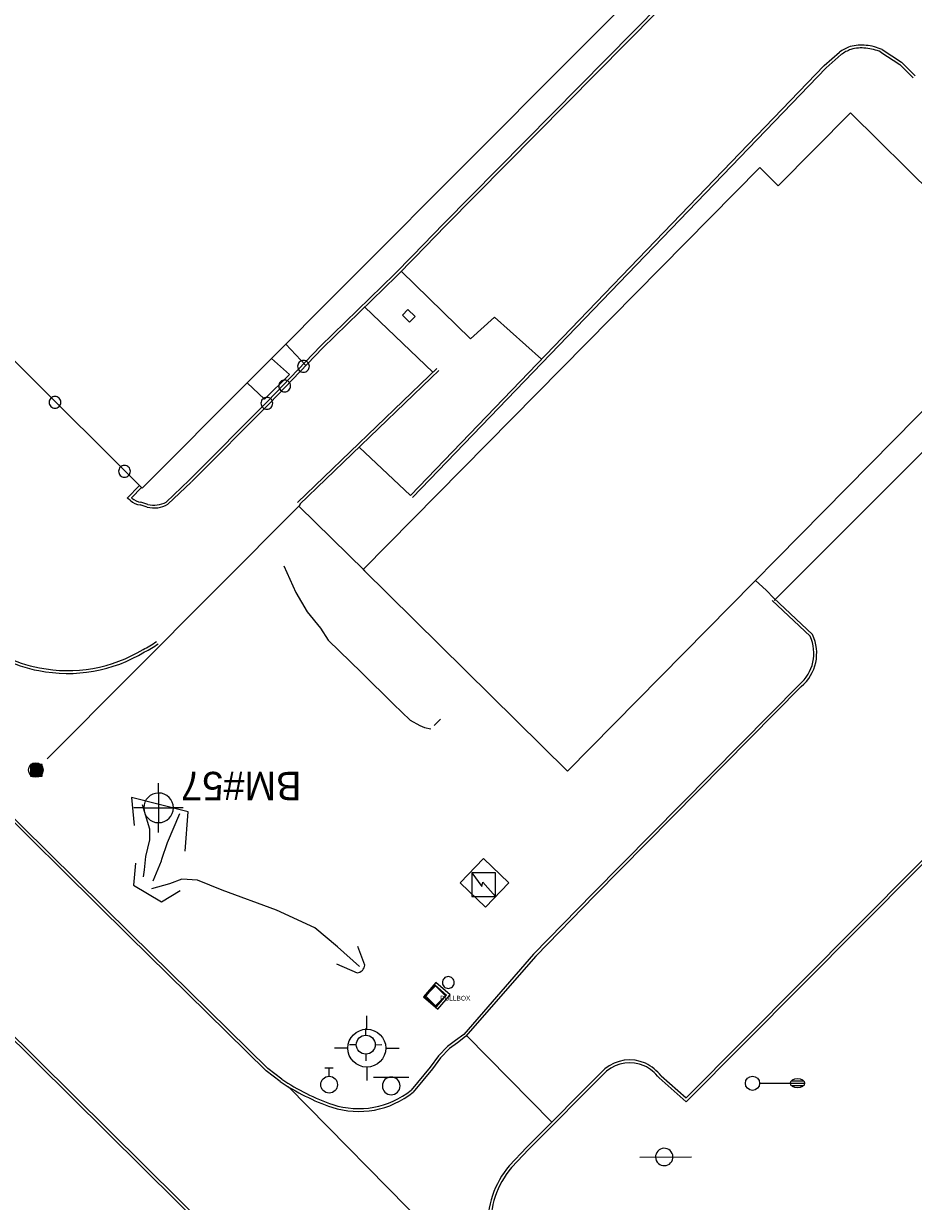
# Model space of a CAD drawing. Extents: x 2145380 to 2156929, y 139568 to 149130.
# Drawn here: x 2151182.3 to 2151370.2, y 143345.6 to 143594.3 of the extents above; entities that cross this region are included whole.
import ezdxf

# ---------------------------------------------------------------- set-up
doc = ezdxf.new("R2010")
doc.units = 0
for name, color, linetype in [('Default', 7, 'Continuous'), ('SURV_Benchmark', 7, 'Continuous'), ('SURV_Text', 7, 'Continuous'), ('TOPO_Asphalt', 7, 'Continuous'), ('TOPO_Building', 7, 'Continuous'), ('TOPO_Concrete', 7, 'Continuous'), ('TOPO_Curb Back', 7, 'Continuous'), ('TOPO_DRAIN_Headwall', 7, 'Continuous'), ('TOPO_DRAIN_Inlet Grate', 7, 'Continuous'), ('TOPO_Flowline', 7, 'Continuous'), ('TOPO_Light Pole', 7, 'Continuous'), ('TOPO_Misc', 7, 'Continuous'), ('TOPO_Pipeline', 7, 'Continuous'), ('TOPO_Power Pullbox', 7, 'Continuous'), ('TOPO_Sidewalk', 7, 'Continuous'), ('TOPO_Sign', 7, 'Continuous'), ('TOPO_Wall Freestanding', 7, 'Continuous'), ('TOPO_Water Fire Hydrant', 7, 'Continuous'), ('TOPO_Water Meter', 7, 'Continuous'), ('TOPO_Water Valve', 7, 'Continuous')]:
    doc.layers.add(name, color=color, linetype=linetype)

# ---------------------------------------------------------------- blocks, each defined once
blk = doc.blocks.new('POST')
at = {"layer": 'TOPO_Misc'}
for start, end in [(89.99996, 180.00004), (179.99996, 270.00004), (359.99996, 90.00004), (269.99996, 0.00004)]:
    blk.add_arc((-0.01, 0.03), 3.16, start, end, dxfattribs=at)
blk = doc.blocks.new('FIRHYD')
at = {"layer": 'TOPO_Water Fire Hydrant'}
for p, q in [((-0.02, 10.16), (-0.03, 17.34)), ((10.16, 0.02), (17.34, 0.03)), ((-10.16, -0.02), (-17.34, -0.03)), ((0.02, -10.16), (0.03, -17.34))]:
    blk.add_line(p, q, dxfattribs=at)
blk.add_circle((0, 0), 10.16, dxfattribs=at)
blk = doc.blocks.new('CB')
at = {"layer": 'TOPO_Misc'}
for p, q in [((-3.08, 2.99), (3.24, 2.99)), ((-3.08, 2.68), (3.24, 2.68)), ((-3.08, 2.36), (3.24, 2.36)), ((-3.08, 2.05), (3.24, 2.05)), ((-3.08, 1.73), (3.24, 1.73)), ((-3.08, 1.4), (3.24, 1.4)), ((-3.08, 1.1), (3.24, 1.1)), ((-3.08, 0.77), (3.24, 0.77)), ((-3.08, 0.46), (3.24, 0.46)), ((-3.08, 0.14), (3.24, 0.14)), ((-3.08, -0.17), (3.24, -0.17)), ((-3.08, -0.48), (3.24, -0.48)), ((-3.08, -0.8), (3.24, -0.8)), ((-3.08, -1.11), (3.26, -1.11)), ((-3.08, -1.43), (3.26, -1.43)), ((-3.08, -1.75), (3.26, -1.75)), ((-3.08, -2.07), (3.26, -2.07)), ((-3.08, -2.39), (3.26, -2.39)), ((-3.08, -2.7), (3.26, -2.7)), ((-3.08, -3.02), (3.26, -3.02))]:
    blk.add_line(p, q, dxfattribs=at)
blk.add_lwpolyline([(3.26, -3.29), (3.24, 3.05), (-3.09, 3.04), (-3.08, -3.3), (3.26, -3.29)], dxfattribs=at)
blk = doc.blocks.new('LP')
at = {"layer": 'TOPO_Light Pole'}
blk.add_line((3.81, 0), (20.32, 0), dxfattribs=at)
for points in [[(20.32, 0), (27.94, 0)], [(20.32, 0), (23.5, 0)], [(20.83, 1.27), (27.43, 1.27)], [(20.83, 1.27), (23.5, 1.27)], [(23.71, 1.27), (27.43, 1.27)], [(23.71, 0), (27.94, 0)], [(20.83, -1.27), (27.43, -1.27)], [(20.83, -1.27), (23.5, -1.27)], [(23.71, -1.27), (27.43, -1.27)]]:
    blk.add_lwpolyline(points, dxfattribs=at)
blk.add_circle((0, 0), 3.81, dxfattribs=at)
blk.add_ellipse((24.13, 0), major_axis=(3.81, 0), ratio=0.666667, dxfattribs=at)
blk = doc.blocks.new('pulbox')
at = {"layer": 'Default'}
blk.add_lwpolyline([(-5.38, -0.01), (-0.02, 5.42), (5.4, 0.06), (0.05, -5.36), (-5.38, -0.01)], dxfattribs=at)
blk.add_text('PULLBOX', height=2.54, dxfattribs=at).set_placement((2.54, -2.54))
blk = doc.blocks.new('WATVAL')
at = {"layer": 'Default'}
for p, q in [((-2.25, 9), (2.25, 9)), ((0, 4.5), (0, 9))]:
    blk.add_line(p, q, dxfattribs=at)
blk.add_circle((0, 0), 4.5, dxfattribs=at)
blk = doc.blocks.new('WTRMTR')
at = {"layer": 'Default'}
blk.add_circle((0, 0), 3.89, dxfattribs=at)
blk = doc.blocks.new('BM')
at = {"layer": 'SURV_Benchmark'}
for p, q in [((0, 2.49), (0, 4.15)), ((-2.49, 0), (-4.16, 0)), ((4.16, 0), (2.49, 0)), ((0, -4.16), (0, -2.49))]:
    blk.add_line(p, q, dxfattribs=at)
for points in [[(0, 2.49), (0, 2.49), (0, 0), (2.49, 0), (2.49, 0), (2.49, 0)], [(0, 2.49), (0, 2.49), (0, 0), (2.49, 0), (2.49, 0), (2.49, 0), (2.49, 0)], [(-2.5, 0), (-2.49, 0), (0, 0), (0, -2.49), (0, -2.49)], [(-2.5, 0), (-2.49, 0), (0, 0), (0, -2.49), (0, -2.49)]]:
    blk.add_lwpolyline(points, dxfattribs=at)
for start, end in [(90.0638, 180.0068), (0.0638, 90.0068), (0.0638, 90.0068), (180.0638, 270.0068), (180.0638, 270.0068), (269.9472, 359.9927)]:
    blk.add_arc((0, 0), 2.5, start, end, dxfattribs=at)

msp = doc.modelspace()

# ---------------------------------------------------------------- linework, layer by layer
at = {"layer": 'TOPO_Asphalt'}
for p, q in [((2151254.31, 143534.41), (2151268.68, 143520.64)), ((2151380.5, 143512.18), (2151340.77, 143472.49)), ((2151293.84, 143362.35), (2151275.8, 143380.63)), ((2151285.56, 143321.77), (2151238.13, 143369.84))]:
    msp.add_line(p, q, dxfattribs=at)
for points in [[(2151262.04, 143541.99), (2151276.66, 143527.7), (2151281.73, 143532.31), (2151291.67, 143523.42)], [(2151340.74, 143472.94), (2151339.09, 143474.63), (2151336.85, 143476.67)]]:
    msp.add_lwpolyline(points, dxfattribs=at)
at = {"layer": 'TOPO_Building'}
for points in [[(2151029.19, 143673.7), (2151207.33, 143496.15), (2151320.89, 143610.09), (2151270.88, 143659.93), (2151269.72, 143669.16), (2151204.55, 143725.48), (2151142.55, 143787.27), (2151057.58, 143702.01), (2151032.57, 143726.94), (2151017.22, 143711.53), (2151042.15, 143686.7)], [(2151254.02, 143479.01), (2151337.75, 143563.85), (2151341.66, 143559.99), (2151356.88, 143575.42), (2151392.22, 143540.54), (2151376.84, 143524.96), (2151380.72, 143521.13), (2151297.15, 143436.44)]]:
    msp.add_lwpolyline(points, close=True, dxfattribs=at)
at = {"layer": 'TOPO_Concrete'}
for points in [[(2151279.4, 143418), (2151284.74, 143412.87), (2151279.8, 143407.72), (2151274.46, 143412.85), (2151279.4, 143418)], [(2151266.72, 143388.83), (2151269.79, 143386.18), (2151272.39, 143389.2), (2151269.32, 143391.85), (2151266.72, 143388.83)], [(2151269.12, 143391.32), (2151266.98, 143388.75), (2151269.45, 143386.66), (2151271.6, 143389.12), (2151269.12, 143391.32)], [(2151269.12, 143391.32), (2151266.98, 143388.75), (2151269.45, 143386.66), (2151271.6, 143389.12), (2151269.12, 143391.32)]]:
    msp.add_lwpolyline(points, dxfattribs=at)
at = {"layer": 'TOPO_Curb Back'}
for points in [[(2151217.23, 143497.85), (2151233.82, 143514.55), (2151244.97, 143526.14), (2151260.58, 143541.36), (2151264.42, 143545.26), (2151271.05, 143552.03), (2151328.28, 143610.03), (2151330.36, 143612.44)], [(2151217.72, 143497.49), (2151234.25, 143514.13), (2151245.39, 143525.72), (2151261, 143540.93), (2151264.84, 143544.84), (2151271.47, 143551.61), (2151328.72, 143609.63), (2151330.85, 143612.08)], [(2151263.96, 143494.63), (2151351.32, 143585.39), (2151354.57, 143588.19)], [(2151264.4, 143494.21), (2151351.74, 143584.95), (2151354.94, 143587.72)], [(2151363.31, 143588.24), (2151367.3, 143585.61), (2151370.14, 143582.81)], [(2151363.6, 143588.76), (2151367.68, 143586.08), (2151370.56, 143583.24)], [(2151478.51, 143087.7), (2151441.77, 143122.28), (2151374.1, 143188.74), (2151297.47, 143264.1), (2151237.35, 143323.07), (2151177.39, 143382.45), (2151154.74, 143404.77), (2151122.02, 143437.29), (2151056.1, 143501.92), (2151038.85, 143519.47), (2151023.07, 143536.96), (2151006.08, 143558.57)], [(2151478.9, 143088.15), (2151442.19, 143122.72), (2151374.52, 143189.17), (2151297.89, 143264.53), (2151237.77, 143323.5), (2151177.82, 143382.87), (2151155.16, 143405.2), (2151122.44, 143437.72), (2151056.52, 143502.34), (2151039.28, 143519.88), (2151023.53, 143537.35), (2151006.56, 143558.93)], [(2151240.11, 143493.14), (2151267.95, 143519.93), (2151269.55, 143521.47)], [(2151240.53, 143492.71), (2151268.36, 143519.5), (2151269.96, 143521.04)], [(2151316.48, 143371.69), (2151322.22, 143366.62), (2151371.2, 143415.91), (2151418.19, 143462.91), (2151454.94, 143500.25), (2151441.58, 143512.8)], [(2151316.91, 143372.1), (2151322.2, 143367.45), (2151370.78, 143416.33), (2151417.77, 143463.34), (2151454.08, 143500.23), (2151441.17, 143512.37)], [(2151217.27, 143497.9), (2151212.4, 143493.26)], [(2151204.79, 143493.62), (2151204.18, 143494.09), (2151206.73, 143496.75)], [(2151205.17, 143494.08), (2151205.08, 143494.15), (2151207.16, 143496.33)], [(2151217.68, 143497.46), (2151212.75, 143492.77)], [(2151208.37, 143492.19), (2151206.92, 143492.63)], [(2151208.53, 143492.76), (2151207.05, 143493.22)], [(2151340.74, 143472.94), (2151348.86, 143465.27)], [(2151340.33, 143472.5), (2151348.36, 143464.91)], [(2151346.1, 143454.75), (2151302.48, 143410.6), (2151289.98, 143397.81), (2151275.22, 143380.88), (2151273.52, 143379.55), (2151271.83, 143378.33), (2151269.88, 143376.33), (2151268.14, 143373.95), (2151264.1, 143369.08)], [(2151346.51, 143454.31), (2151302.91, 143410.17), (2151290.42, 143397.41), (2151275.63, 143380.44), (2151273.88, 143379.07), (2151272.23, 143377.88), (2151270.34, 143375.94), (2151268.61, 143373.58), (2151264.52, 143368.65)], [(2151236.43, 143370.93), (2151233.47, 143373.21), (2151204.5, 143401.65), (2151169.83, 143435.88), (2151157.1, 143448.29)], [(2151236.78, 143371.42), (2151233.87, 143373.67), (2151204.93, 143402.08), (2151170.25, 143436.31), (2151157.52, 143448.72)], [(2151284.85, 143353.15), (2151288.56, 143357.04), (2151305, 143373.58)], [(2151285.29, 143352.75), (2151288.99, 143356.62), (2151305.4, 143373.14)]]:
    msp.add_lwpolyline(points, dxfattribs=at)
for centre, radius, start, end in [((2151359.17, 143580.92), 8.79, 83.1962, 105.5065), ((2151359.35, 143579.46), 10.23, 65.4726, 85.197), ((2151360.02, 143580.72), 9.25, 110.2868, 126.1473), ((2151360.02, 143580.72), 8.64, 110.4522, 125.99), ((2151359.17, 143580.92), 8.19, 83.1236, 105.3309), ((2151359.35, 143579.46), 9.63, 65.7422, 85.2625), ((2151207.57, 143496.84), 4.26, 229.1307, 261.1488), ((2151207.57, 143496.84), 3.66, 228.9113, 261.8019), ((2151209.82, 143498.03), 6.02, 256.0332, 299.177), ((2151209.82, 143498.03), 5.42, 256.2005, 298.3938), ((2151340.64, 143461.3), 9.13, 310.0199, 25.7947), ((2151191.01, 143487.35), 30.2, 228.8088, 259.4658), ((2151191.01, 143487.35), 29.6, 228.8048, 259.4731), ((2151199.93, 143478.12), 17.7, 295.367, 306.0366), ((2151199.93, 143478.12), 18.3, 295.4652, 306.0363), ((2151340.64, 143461.3), 8.53, 309.8365, 25.0646), ((2151191.58, 143488.35), 31.28, 258.7721, 301.2211), ((2151191.58, 143488.35), 30.68, 258.7653, 301.2776), ((2151310.3, 143367.11), 8.37, 66.6777, 129.3015), ((2151310.3, 143367.11), 7.77, 66.8347, 129.0773), ((2151308.81, 143365.52), 9.85, 38.7905, 62.4758), ((2151308.81, 143365.52), 10.45, 39.0769, 62.6013), ((2151262.94, 143410.48), 47.61, 236.1731, 250.9257), ((2151262.94, 143410.48), 47.01, 236.1971, 250.9181), ((2151253.02, 143382.95), 18.35, 252.0944, 308.8042), ((2151253.02, 143382.95), 17.75, 252.1139, 308.6106), ((2151299.82, 143340.58), 19.55, 140.0019, 182.664), ((2151299.82, 143340.58), 18.95, 140.0587, 182.7511)]:
    msp.add_arc(centre, radius, start, end, dxfattribs=at)
at = {"layer": 'TOPO_DRAIN_Headwall'}
for points in [[(2151216.42, 143419.55), (2151217.02, 143427.84), (2151205.08, 143430.9), (2151205.61, 143424.96)], [(2151205.92, 143417.03), (2151205.45, 143412.41), (2151211.41, 143408.88), (2151215.34, 143411.22)], [(2151254.35, 143395.51), (2151252.88, 143399.44)], [(2151248.33, 143395.77), (2151252.71, 143393.85)]]:
    msp.add_lwpolyline(points, dxfattribs=at)
msp.add_arc((2151252.45, 143395.74), 1.92, 277.7043, 352.9027, dxfattribs=at)
at = {"layer": 'TOPO_DRAIN_Inlet Grate'}
msp.add_lwpolyline([(2151262.28, 143532.68), (2151263.8, 143531.24), (2151264.94, 143532.44), (2151263.42, 143533.88)], close=True, dxfattribs=at)
at = {"layer": 'TOPO_Flowline'}
for points in [[(2151237.26, 143479.78), (2151239.79, 143474.13), (2151242.13, 143470.07), (2151244.96, 143466.62), (2151246.6, 143464.13), (2151253.62, 143457.29), (2151260.4, 143450.57), (2151263.91, 143447.2), (2151265.93, 143446.1), (2151266.96, 143445.69), (2151268.31, 143445.35)], [(2151207.31, 143429.38), (2151208.89, 143424.24), (2151208.89, 143421.93), (2151208.05, 143418.46), (2151207.73, 143415.62), (2151207.52, 143414.15)], [(2151209.62, 143413.31), (2151211.4, 143417.5), (2151211.44, 143417.86), (2151212.67, 143421.4), (2151215.29, 143427.49)], [(2151253.23, 143395.2), (2151248.59, 143399.34), (2151243.76, 143403.34), (2151235.67, 143407.12), (2151224.22, 143411.32), (2151218.97, 143413.42), (2151215.71, 143413.63), (2151213.08, 143412.68), (2151209.31, 143411.63)]]:
    msp.add_lwpolyline(points, dxfattribs=at)
at = {"layer": 'TOPO_Misc'}
for points in [[(2151281.94, 143409.97), (2151281.93, 143414.96), (2151276.94, 143414.96), (2151276.95, 143409.96), (2151281.94, 143409.97)], [(2151276.94, 143414.96), (2151279.05, 143412.09), (2151279.27, 143413.03), (2151281.94, 143409.97)]]:
    msp.add_lwpolyline(points, dxfattribs=at)
at = {"layer": 'TOPO_Pipeline'}
msp.add_line((2151270.32, 143447.45), (2151268.98, 143446.07), dxfattribs=at)
at = {"layer": 'TOPO_Sidewalk'}
for p, q in [((2151237.63, 143526.55), (2151241.88, 143522.07)), ((2151240.43, 143492.41), (2151254.32, 143478.72))]:
    msp.add_line(p, q, dxfattribs=at)
at = {"layer": 'TOPO_Sign'}
for points in [[(2151256.16, 143371.87), (2151263.65, 143371.87)], [(2151259.91, 143371.86), (2151259.91, 143371.86)], [(2151258.04, 143370), (2151258.04, 143370)], [(2151261.78, 143370), (2151261.78, 143370)], [(2151259.91, 143368.13), (2151259.91, 143368.13)], [(2151312.44, 143354.98), (2151323.32, 143355.04)]]:
    msp.add_lwpolyline(points, dxfattribs=at)
for centre, radius, start, end in [((2151259.91, 143370), 1.87, 90, 180), ((2151259.91, 143370), 1.87, 360, 90), ((2151259.91, 143370), 1.87, 180, 270), ((2151259.91, 143370), 1.87, 270, 0), ((2151317.57, 143355), 1.84, 47.4196, 227.4196), ((2151317.57, 143355), 1.84, 227.4196, 47.4196)]:
    msp.add_arc(centre, radius, start, end, dxfattribs=at)
at = {"layer": 'TOPO_Wall Freestanding'}
for p, q in [((2151253.11, 143504.81), (2151263.96, 143494.63)), ((2151187.24, 143439.07), (2151240.75, 143492.73))]:
    msp.add_line(p, q, dxfattribs=at)
msp.add_lwpolyline([(2151229.52, 143518.41), (2151233.15, 143514.94), (2151238.4, 143520.17), (2151234.62, 143523.53)], dxfattribs=at)

# ---------------------------------------------------------------- block references
at = {"layer": 'SURV_Benchmark', "xscale": 1.25, "yscale": 1.25}
msp.add_blockref('BM', (2151210.78, 143428.7), dxfattribs=at)
at = {"layer": 'TOPO_Light Pole', "xscale": 0.39370000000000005, "yscale": 0.3937000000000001}
msp.add_blockref('LP', (2151336.21, 143370.56), dxfattribs=at)
at = {"layer": 'TOPO_Misc', "xscale": 0.39370000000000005, "yscale": 0.3937000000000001}
for name, p in [('POST', (2151241.39, 143521.9)), ('POST', (2151237.4, 143517.76)), ('POST', (2151188.91, 143514.28)), ('POST', (2151233.65, 143514.1)), ('POST', (2151203.58, 143499.74)), ('CB', (2151184.94, 143436.67)), ('POST', (2151271.96, 143391.81))]:
    msp.add_blockref(name, p, dxfattribs=at)
at = {"layer": 'TOPO_Power Pullbox', "xscale": 0.39370000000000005, "yscale": 0.3937000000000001}
msp.add_blockref('pulbox', (2151269.25, 143389.02), dxfattribs=at)
at = {"layer": 'TOPO_Water Fire Hydrant'}
for p, xscale, yscale in [((2151254.75, 143377.97), 0.39370000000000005, 0.3937000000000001), ((2151254.54, 143378.7), 0.19685000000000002, 0.19685000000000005)]:
    msp.add_blockref('FIRHYD', p, dxfattribs=dict(at, xscale=xscale, yscale=yscale))
at = {"layer": 'TOPO_Water Meter', "xscale": 0.39370000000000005, "yscale": 0.3937000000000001}
msp.add_blockref('WTRMTR', (2151184.85, 143436.69), dxfattribs=at)
at = {"layer": 'TOPO_Water Valve', "xscale": 0.39370000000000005, "yscale": 0.3937000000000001}
msp.add_blockref('WATVAL', (2151246.79, 143370.26), dxfattribs=at)

# ---------------------------------------------------------------- texts
at = {"layer": 'SURV_Text'}
msp.add_text('BM#57', height=6, rotation=180, dxfattribs=at).set_placement((2151240.95, 143436.3))

doc.saveas('drawing.dxf')
